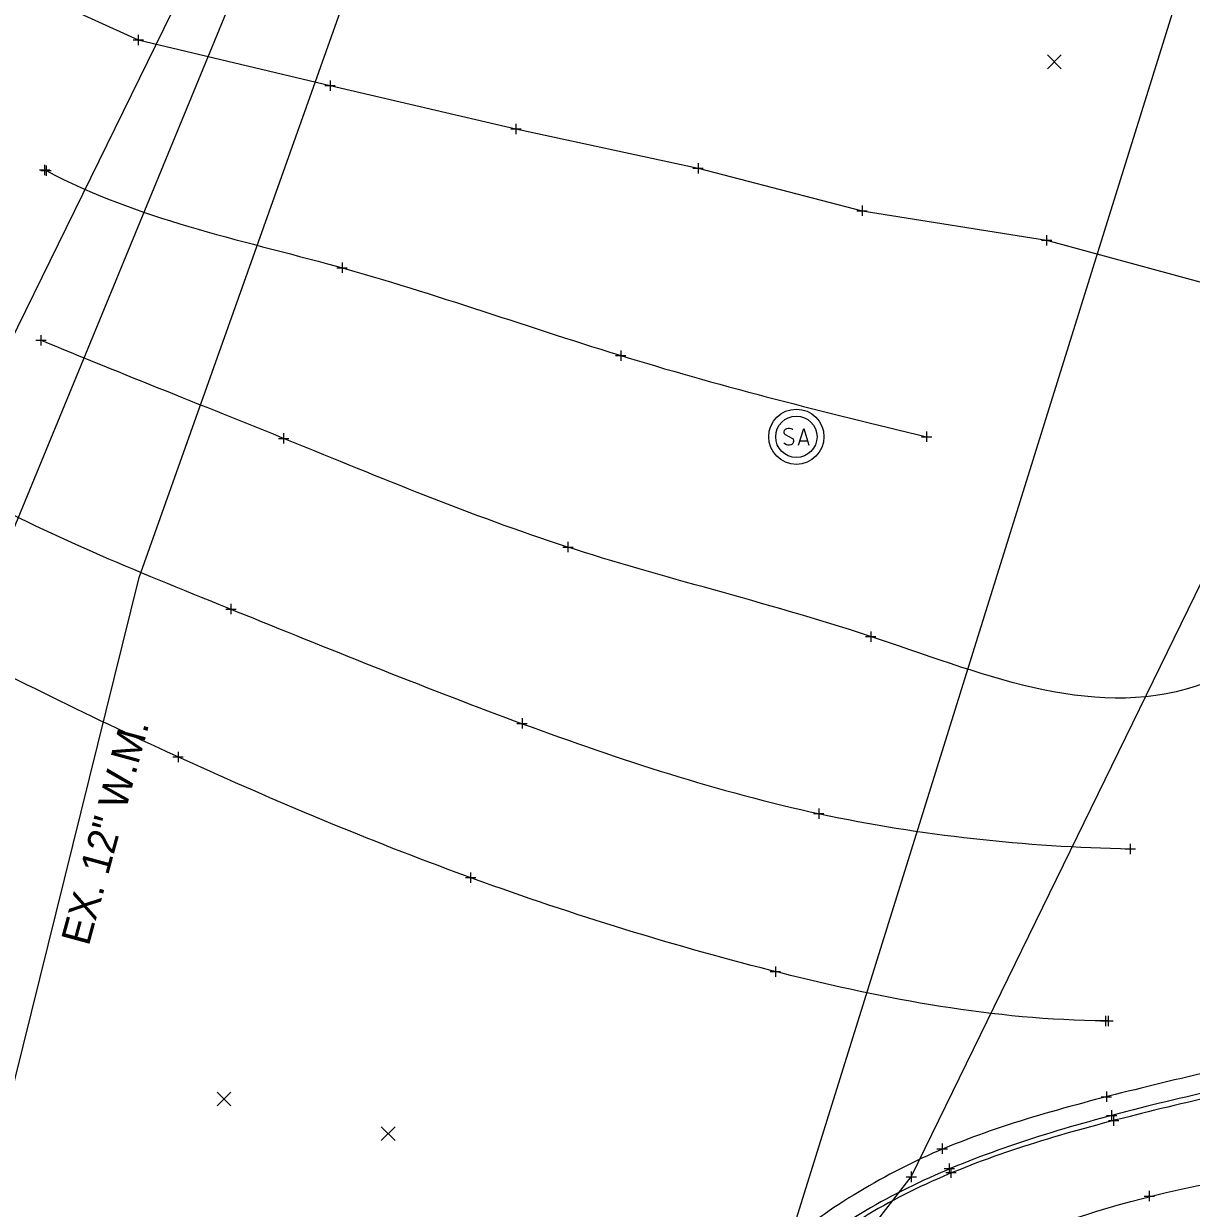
# Model space of a CAD drawing. Extents: x 1324089 to 1329959, y 459099 to 462017.
# Drawn here: x 1324710.1 to 1324823, y 459381.3 to 459495.9 of the extents above; entities that cross this region are included whole.
import ezdxf

# ---------------------------------------------------------------- set-up
doc = ezdxf.new("R2010")
doc.units = 0
for name, color, linetype in [('DR_X_Storm_Sewer', 7, 'Continuous'), ('GK_Drainage_Nodes', 7, 'Continuous'), ('PV_X_Curb', 7, 'Continuous'), ('PV_X_EOP', 7, 'Continuous'), ('SV_X_Break_Lines', 7, 'Continuous'), ('SV_X_Random_Point', 7, 'Continuous'), ('SV_X_Shot_Marker', 7, 'Continuous'), ('UT_X_Electric', 7, 'Continuous'), ('UT_X_Sanitary_Cells', 7, 'Continuous'), ('UT_X_Telecom', 7, 'Continuous'), ('UT_X_Water', 7, 'Continuous'), ('UT_X_Water_Text', 7, 'Continuous')]:
    doc.layers.add(name, color=color, linetype=linetype)

msp = doc.modelspace()

# ---------------------------------------------------------------- linework, layer by layer
at = {"layer": 'DR_X_Storm_Sewer'}
msp.add_line((1324829.48, 459523.47), (1324778.26, 459359.26), dxfattribs=at)
at = {"layer": 'GK_Drainage_Nodes'}
for p, q in [((1324784.84, 459457.94), (1324784.84, 459457.94)), ((1324784.84, 459455.94), (1324784.84, 459455.94)), ((1324784.84, 459455.94), (1324784.84, 459455.94)), ((1324784.84, 459455.94), (1324784.84, 459455.94)), ((1324784.84, 459453.94), (1324784.84, 459453.94))]:
    msp.add_line(p, q, dxfattribs=at)
msp.add_circle((1324784.84, 459455.94), 2, dxfattribs=at)
at = {"layer": 'PV_X_Curb'}
for points in [[(1324886.94, 459397.2), (1324879.16, 459397.33), (1324863.08, 459397.34), (1324839.01, 459395.74), (1324817.61, 459391.19), (1324798.89, 459385.61), (1324782.82, 459376.4), (1324776.01, 459366.12), (1324773.37, 459359.99)], [(1324886.77, 459396.67), (1324879.14, 459396.87), (1324863.06, 459396.83), (1324839.14, 459395.28), (1324817.79, 459390.62), (1324799.05, 459385.28), (1324783.17, 459375.99), (1324776.45, 459365.83), (1324773.86, 459359.8)]]:
    msp.add_open_spline(points, degree=3, dxfattribs=at)
at = {"layer": 'PV_X_EOP'}
msp.add_open_spline([(1324886.79, 459399.19), (1324879.04, 459399.08), (1324862.89, 459399.49), (1324838.65, 459397.73), (1324817.21, 459392.88), (1324797.87, 459387.59), (1324787.82, 459381.25), (1324782.76, 459377.22)], degree=3, dxfattribs=at)
at = {"layer": 'SV_X_Break_Lines'}
for p, q in [((1324712.14, 459481.74), (1324712.28, 459481.67)), ((1324814.99, 459399.45), (1324814.75, 459399.46))]:
    msp.add_line(p, q, dxfattribs=at)
msp.add_lwpolyline([(1324707.53, 459500.55), (1324721.2, 459494.32), (1324739.75, 459489.9), (1324757.72, 459485.71), (1324775.33, 459481.91), (1324791.2, 459477.79), (1324809.04, 459474.94), (1324827.89, 459469.83)], dxfattribs=at)
for points in [[(1324712.28, 459481.67), (1324721.16, 459476.97), (1324740.59, 459473.14), (1324768.44, 459463.1), (1324787.51, 459458.32), (1324797.44, 459455.94)], [(1324824.47, 459432.18), (1324814.21, 459428.21), (1324792.26, 459437.56), (1324763.03, 459444.31), (1324736.5, 459455.37), (1324719.58, 459462.04), (1324711.78, 459465.27)], [(1324706.01, 459449.96), (1324713.79, 459445.84), (1324731.38, 459438.81), (1324758.07, 459427.94), (1324786.92, 459418.42), (1324806.9, 459416.33), (1324817.13, 459416.09)], [(1324814.75, 459399.46), (1324803.89, 459399.55), (1324783.11, 459403.55), (1324753.24, 459412.83), (1324726.23, 459424.14), (1324709.21, 459432.46), (1324701.45, 459436.56)], [(1324758.84, 459218.38), (1324759.03, 459223.35), (1324758.93, 459236.5), (1324761.05, 459255.91), (1324762.78, 459277.36), (1324764.69, 459298.91), (1324768.89, 459321.85), (1324772.52, 459342.12), (1324779.19, 459358.73), (1324789.11, 459371.52), (1324804.35, 459377.96), (1324821.07, 459383.64), (1324841.95, 459386.23), (1324864.43, 459389.81), (1324886.84, 459390.45), (1324905.55, 459391.13), (1324922.61, 459391.44), (1324932.95, 459392.39), (1324937.78, 459392.93)]]:
    msp.add_open_spline(points, degree=3, dxfattribs=at)
at = {"layer": 'SV_X_Random_Point'}
for p, q in [((1324809.12, 459491.52), (1324810.45, 459492.86)), ((1324809.12, 459492.86), (1324810.45, 459491.52)), ((1324728.82, 459391.23), (1324730.15, 459392.56)), ((1324728.82, 459392.56), (1324730.15, 459391.23)), ((1324744.7, 459387.9), (1324746.03, 459389.23)), ((1324744.7, 459389.23), (1324746.03, 459387.9))]:
    msp.add_line(p, q, dxfattribs=at)
at = {"layer": 'SV_X_Shot_Marker'}
for p, q in [((1324720.7, 459494.32), (1324721.7, 459494.32)), ((1324721.2, 459494.82), (1324721.2, 459493.82)), ((1324721.2, 459494.32), (1324721.2, 459494.32)), ((1324739.75, 459490.4), (1324739.75, 459489.4)), ((1324739.25, 459489.9), (1324740.25, 459489.9)), ((1324739.75, 459489.9), (1324739.75, 459489.9)), ((1324757.72, 459486.21), (1324757.72, 459485.21)), ((1324757.22, 459485.71), (1324758.22, 459485.71)), ((1324757.72, 459485.71), (1324757.72, 459485.71)), ((1324775.33, 459482.41), (1324775.33, 459481.41)), ((1324711.64, 459481.74), (1324712.64, 459481.74)), ((1324711.78, 459481.67), (1324712.78, 459481.67)), ((1324712.14, 459482.24), (1324712.14, 459481.24)), ((1324712.14, 459481.74), (1324712.14, 459481.74)), ((1324712.28, 459482.17), (1324712.28, 459481.17)), ((1324712.28, 459481.67), (1324712.28, 459481.67)), ((1324774.83, 459481.91), (1324775.83, 459481.91)), ((1324775.33, 459481.91), (1324775.33, 459481.91)), ((1324790.7, 459477.79), (1324791.7, 459477.79)), ((1324791.2, 459478.29), (1324791.2, 459477.29)), ((1324791.2, 459477.79), (1324791.2, 459477.79)), ((1324808.54, 459474.94), (1324809.54, 459474.94)), ((1324809.04, 459475.44), (1324809.04, 459474.44)), ((1324809.04, 459474.94), (1324809.04, 459474.94)), ((1324740.41, 459472.28), (1324741.41, 459472.28)), ((1324740.91, 459472.78), (1324740.91, 459471.78)), ((1324740.91, 459472.28), (1324740.91, 459472.28)), ((1324711.28, 459465.27), (1324712.28, 459465.27)), ((1324711.78, 459465.77), (1324711.78, 459464.77)), ((1324711.78, 459465.27), (1324711.78, 459465.27)), ((1324767.85, 459464.29), (1324767.85, 459463.29)), ((1324767.35, 459463.79), (1324768.35, 459463.79)), ((1324767.85, 459463.79), (1324767.85, 459463.79)), ((1324735.25, 459456.28), (1324735.25, 459455.28)), ((1324797.44, 459456.44), (1324797.44, 459455.44)), ((1324734.75, 459455.78), (1324735.75, 459455.78)), ((1324735.25, 459455.78), (1324735.25, 459455.78)), ((1324796.94, 459455.94), (1324797.94, 459455.94)), ((1324797.44, 459455.94), (1324797.44, 459455.94)), ((1324762.75, 459445.77), (1324762.75, 459444.77)), ((1324762.25, 459445.27), (1324763.25, 459445.27)), ((1324762.75, 459445.27), (1324762.75, 459445.27)), ((1324729.66, 459439.27), (1324730.66, 459439.27)), ((1324730.16, 459439.77), (1324730.16, 459438.77)), ((1324730.16, 459439.27), (1324730.16, 459439.27)), ((1324791.54, 459436.62), (1324792.54, 459436.62)), ((1324792.04, 459437.12), (1324792.04, 459436.12)), ((1324792.04, 459436.62), (1324792.04, 459436.62)), ((1324758.31, 459428.72), (1324758.31, 459427.72)), ((1324757.81, 459428.22), (1324758.81, 459428.22)), ((1324758.31, 459428.22), (1324758.31, 459428.22)), ((1324725.04, 459425.48), (1324725.04, 459424.48)), ((1324724.54, 459424.98), (1324725.54, 459424.98)), ((1324725.04, 459424.98), (1324725.04, 459424.98)), ((1324786.5, 459419.5), (1324787.5, 459419.5)), ((1324787, 459420), (1324787, 459419)), ((1324787, 459419.5), (1324787, 459419.5)), ((1324816.63, 459416.09), (1324817.63, 459416.09)), ((1324817.13, 459416.59), (1324817.13, 459415.59)), ((1324817.13, 459416.09), (1324817.13, 459416.09)), ((1324753.33, 459413.82), (1324753.33, 459412.82)), ((1324752.83, 459413.32), (1324753.83, 459413.32)), ((1324753.33, 459413.32), (1324753.33, 459413.32)), ((1324782.81, 459404.73), (1324782.81, 459403.73)), ((1324782.31, 459404.23), (1324783.31, 459404.23)), ((1324782.81, 459404.23), (1324782.81, 459404.23)), ((1324814.75, 459399.96), (1324814.75, 459398.96)), ((1324814.99, 459399.95), (1324814.99, 459398.95)), ((1324814.25, 459399.46), (1324815.25, 459399.46)), ((1324814.49, 459399.45), (1324815.49, 459399.45)), ((1324814.75, 459399.46), (1324814.75, 459399.46)), ((1324814.99, 459399.45), (1324814.99, 459399.45)), ((1324814.33, 459392.12), (1324815.33, 459392.12)), ((1324814.83, 459392.62), (1324814.83, 459391.62)), ((1324814.83, 459392.12), (1324814.83, 459392.12)), ((1324815.32, 459390.82), (1324815.32, 459389.82)), ((1324814.82, 459390.32), (1324815.82, 459390.32)), ((1324815.02, 459389.82), (1324816.02, 459389.82)), ((1324815.32, 459390.32), (1324815.32, 459390.32)), ((1324815.52, 459390.32), (1324815.52, 459389.32)), ((1324815.52, 459389.82), (1324815.52, 459389.82)), ((1324798.94, 459387.6), (1324798.94, 459386.6)), ((1324798.44, 459387.1), (1324799.44, 459387.1)), ((1324798.94, 459387.1), (1324798.94, 459387.1)), ((1324799.12, 459385.18), (1324800.12, 459385.18)), ((1324799.62, 459385.68), (1324799.62, 459384.68)), ((1324799.62, 459385.18), (1324799.62, 459385.18)), ((1324799.79, 459385.29), (1324799.79, 459384.29)), ((1324795.45, 459384.38), (1324796.45, 459384.38)), ((1324795.95, 459384.88), (1324795.95, 459383.88)), ((1324795.95, 459384.38), (1324795.95, 459384.38)), ((1324799.29, 459384.79), (1324800.29, 459384.79)), ((1324799.79, 459384.79), (1324799.79, 459384.79)), ((1324818.97, 459383.02), (1324818.97, 459382.02)), ((1324818.47, 459382.52), (1324819.47, 459382.52)), ((1324818.97, 459382.52), (1324818.97, 459382.52))]:
    msp.add_line(p, q, dxfattribs=at)
at = {"layer": 'UT_X_Electric'}
for points in [[(1324664.08, 459448.47), (1324671.98, 459443.31), (1324679.66, 459437.99), (1324686.09, 459432.8), (1324688.36, 459430.7), (1324693.78, 459434.48), (1324728.42, 459505.08)], [(1324783.82, 459370.21), (1324786.83, 459372.62), (1324795.95, 459384.38), (1324840.15, 459474.88), (1324844.76, 459482.31), (1324844.41, 459484.94), (1324844.25, 459490.75), (1324841.91, 459497.67)]]:
    msp.add_lwpolyline(points, dxfattribs=at)
at = {"layer": 'UT_X_Sanitary_Cells'}
for points in [[(1324784.51, 459456.63), (1324784.48, 459456.65), (1324784.44, 459456.68), (1324784.33, 459456.72), (1324784.19, 459456.74), (1324784.09, 459456.74), (1324784.05, 459456.74), (1324783.89, 459456.7), (1324783.75, 459456.63), (1324783.66, 459456.53), (1324783.64, 459456.43), (1324783.64, 459456.35), (1324783.66, 459456.25), (1324783.76, 459456.16), (1324784.45, 459455.78), (1324784.52, 459455.73), (1324784.54, 459455.68), (1324784.57, 459455.61), (1324784.57, 459455.53), (1324784.56, 459455.46), (1324784.54, 459455.41), (1324784.52, 459455.34), (1324784.49, 459455.29), (1324784.47, 459455.25), (1324784.43, 459455.22), (1324784.39, 459455.19), (1324784.34, 459455.17), (1324784.3, 459455.15), (1324784.19, 459455.14), (1324784.01, 459455.14), (1324783.9, 459455.17), (1324783.74, 459455.25), (1324783.64, 459455.33)], [(1324785.05, 459455.14), (1324785.55, 459456.74), (1324786.04, 459455.14)], [(1324785.92, 459455.52), (1324785.17, 459455.52)]]:
    msp.add_lwpolyline(points, dxfattribs=at)
for radius in [2.67, 2]:
    msp.add_circle((1324784.84, 459455.94), radius, dxfattribs=at)
at = {"layer": 'UT_X_Telecom'}
msp.add_lwpolyline([(1324698.77, 459420.1), (1324700.91, 459427.07), (1324737.48, 459515.82), (1324737.41, 459516.05), (1324738.82, 459521.95), (1324747.97, 459550.79), (1324751.86, 459563.44), (1324759.06, 459579.95), (1324766.89, 459595.14), (1324775.63, 459611.51), (1324784.38, 459628.32), (1324792.04, 459644.48), (1324803.66, 459666.95), (1324811.53, 459682.37), (1324815.2, 459692.64), (1324816.71, 459699.25), (1324819.16, 459705.84), (1324820.47, 459711.84), (1324822.07, 459721.29), (1324822.1, 459726.69), (1324822.02, 459731.99), (1324820.97, 459738.06), (1324819.84, 459744.29)], dxfattribs=at)
at = {"layer": 'UT_X_Water'}
msp.add_lwpolyline([(1324683.28, 459219.36), (1324691.61, 459298.59), (1324698.63, 459347.92), (1324699.63, 459354.94), (1324721.27, 459442.34), (1324756.06, 459540.19), (1324772.19, 459580.09), (1324802.34, 459646.28), (1324825.1, 459690.99), (1324841.26, 459722.73), (1324902.17, 459810.08), (1324917.22, 459828.86)], dxfattribs=at)

# ---------------------------------------------------------------- texts
at = {"layer": 'UT_X_Water_Text'}
msp.add_text('EX. 12" W.M.', height=2.8, rotation=74.7595, dxfattribs=at).set_placement((1324716.4, 459406.62))

doc.saveas('drawing.dxf')
